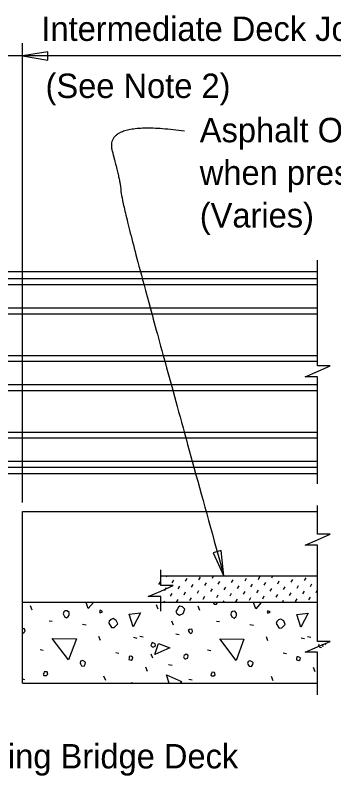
# Model space of a CAD drawing. Extents: x 21516.9 to 21586.2, y 56155.7 to 56195.
# Drawn here: x 21529.91 to 21532.55, y 56169.83 to 56176.11 of the extents above; entities that cross this region are included whole.
import ezdxf

# ---------------------------------------------------------------- set-up
doc = ezdxf.new("R2010")
doc.units = 0
for name, color, linetype in [('AdhocPoint_dp', 7, 'Continuous'), ('Border', 7, 'Continuous'), ('PlotBorder_dp', 7, 'Continuous'), ('SheetBorder_dp', 7, 'Continuous'), ('TextMisc', 7, 'Continuous')]:
    doc.layers.add(name, color=color, linetype=linetype)

msp = doc.modelspace()

# ---------------------------------------------------------------- linework, layer by layer
at = {"layer": 'AdhocPoint_dp'}
for p, q in [((21529.9739, 56170.5954), (21529.9739, 56172.0121)), ((21529.9739, 56172.0121), (21532.4121, 56172.0121)), ((21531.1155, 56171.481), (21532.4121, 56171.481)), ((21532.4121, 56171.2621), (21529.9739, 56171.2621)), ((21529.9739, 56170.5954), (21532.4121, 56170.5954))]:
    msp.add_line(p, q, dxfattribs=at)
at = {"layer": 'Border'}
for p, q in [((21531.1613, 56171.4724), (21531.1663, 56171.481)), ((21531.4314, 56171.4495), (21531.4444, 56171.4719)), ((21531.5421, 56171.4624), (21531.5528, 56171.481)), ((21531.6527, 56171.4754), (21531.6559, 56171.481)), ((21531.9228, 56171.4525), (21531.9358, 56171.4749)), ((21532.0334, 56171.4655), (21532.0424, 56171.481)), ((21532.1441, 56171.4784), (21532.1456, 56171.481)), ((21532.3035, 56171.4425), (21532.3165, 56171.4649)), ((21531.0995, 56171.4106), (21531.1125, 56171.433)), ((21531.2102, 56171.4235), (21531.2231, 56171.4459)), ((21531.3208, 56171.4365), (21531.3338, 56171.4589)), ((21531.3696, 56171.3877), (21531.3826, 56171.4101)), ((21531.4803, 56171.4006), (21531.4932, 56171.423)), ((21531.5909, 56171.4136), (21531.6039, 56171.436)), ((21531.7015, 56171.4266), (21531.7145, 56171.449)), ((21531.7504, 56171.3777), (21531.7633, 56171.4001)), ((21531.8122, 56171.4395), (21531.8251, 56171.4619)), ((21531.861, 56171.3907), (21531.874, 56171.4131)), ((21531.9716, 56171.4037), (21531.9846, 56171.426)), ((21532.0823, 56171.4166), (21532.0952, 56171.439)), ((21532.1929, 56171.4296), (21532.2059, 56171.452)), ((21532.2417, 56171.3807), (21532.2547, 56171.4031)), ((21532.3524, 56171.3937), (21532.3653, 56171.4161)), ((21531.1484, 56171.3617), (21531.1613, 56171.3841)), ((21531.259, 56171.3747), (21531.272, 56171.3971)), ((21531.3078, 56171.3259), (21531.3208, 56171.3483)), ((21531.4185, 56171.3388), (21531.4314, 56171.3612)), ((21531.5291, 56171.3518), (21531.5421, 56171.3742)), ((21531.6397, 56171.3648), (21531.6527, 56171.3872)), ((21531.6886, 56171.3159), (21531.7015, 56171.3383)), ((21531.7992, 56171.3289), (21531.8122, 56171.3513)), ((21531.9098, 56171.3419), (21531.9228, 56171.3642)), ((21532.0205, 56171.3548), (21532.0334, 56171.3772)), ((21532.1311, 56171.3678), (21532.1441, 56171.3902)), ((21532.1799, 56171.3189), (21532.1929, 56171.3413)), ((21532.2906, 56171.3319), (21532.3035, 56171.3543)), ((21532.4012, 56171.3449), (21532.4121, 56171.3638)), ((21531.1972, 56171.3129), (21531.2102, 56171.3353)), ((21531.246, 56171.2641), (21531.259, 56171.2865)), ((21531.3567, 56171.277), (21531.3696, 56171.2994)), ((21531.4673, 56171.29), (21531.4803, 56171.3124)), ((21531.5779, 56171.303), (21531.5909, 56171.3254)), ((21531.6314, 56171.2621), (21531.6397, 56171.2765)), ((21531.7374, 56171.2671), (21531.7504, 56171.2895)), ((21531.848, 56171.2801), (21531.861, 56171.3024)), ((21531.9587, 56171.293), (21531.9716, 56171.3154)), ((21532.0693, 56171.306), (21532.0823, 56171.3284)), ((21532.121, 56171.2621), (21532.1311, 56171.2795)), ((21532.2288, 56171.2701), (21532.2417, 56171.2925)), ((21532.3394, 56171.2831), (21532.3524, 56171.3055)), ((21530.0541, 56171.1989), (21530.04, 56171.2343)), ((21531.0947, 56171.2071), (21531.0806, 56171.2425)), ((21531.1418, 56171.2621), (21531.1484, 56171.2735)), ((21531.4388, 56171.1954), (21531.4247, 56171.2308)), ((21531.5283, 56171.2621), (21531.5291, 56171.2636)), ((21532.0179, 56171.2621), (21532.0205, 56171.2666)), ((21530.192, 56171.1105), (21530.2168, 56171.107)), ((21531.2202, 56171.0746), (21531.2079, 56171.1082)), ((21531.5767, 56171.107), (21531.6015, 56171.1035)), ((21530.4678, 56171.0823), (21530.4979, 56171.077)), ((21531.8525, 56171.0787), (21531.8825, 56171.0734)), ((21530.6163, 56170.9479), (21530.6039, 56170.9815)), ((21530.8903, 56170.9744), (21530.9186, 56170.9674)), ((21530.9427, 56170.9844), (21530.971, 56170.9773)), ((21531.2391, 56171.0027), (21531.2691, 56170.9974)), ((21532.001, 56170.9444), (21531.9886, 56170.978)), ((21532.275, 56170.9709), (21532.3033, 56170.9638)), ((21532.3274, 56170.9809), (21532.3557, 56170.9738)), ((21530.1178, 56170.8737), (21530.1443, 56170.8684)), ((21530.7436, 56170.8489), (21530.7701, 56170.8436)), ((21531.0488, 56170.8018), (21531.0364, 56170.8354)), ((21531.5025, 56170.8701), (21531.529, 56170.8648)), ((21532.1283, 56170.8454), (21532.1548, 56170.8401)), ((21531.0063, 56170.6922), (21530.9922, 56170.7276)), ((21531.179, 56170.7482), (21531.2108, 56170.7446)), ((21532.391, 56170.6887), (21532.3769, 56170.724)), ((21530.6605, 56170.6173), (21530.6464, 56170.6527)), ((21532.0452, 56170.6138), (21532.031, 56170.6492)), ((21529.9739, 56170.6303), (21529.9905, 56170.6262)), ((21531.3469, 56170.6297), (21531.3752, 56170.6226))]:
    msp.add_line(p, q, dxfattribs=at)
for points in [[(21530.5155, 56171.2113), (21530.499, 56171.2621)], [(21530.5585, 56171.2621), (21530.5155, 56171.2113)], [(21531.2485, 56171.17), (21531.2715, 56171.1576), (21531.3016, 56171.17), (21531.3139, 56171.2071), (21531.2963, 56171.2248), (21531.2733, 56171.2301), (21531.2627, 56171.2231), (21531.2503, 56171.2036), (21531.2415, 56171.1877), (21531.2485, 56171.17)], [(21531.5487, 56171.2621), (21531.5573, 56171.2467), (21531.5767, 56171.2484), (21531.5855, 56171.2608), (21531.5857, 56171.2621)], [(21531.9002, 56171.2078), (21531.8825, 56171.2621)], [(21531.9462, 56171.2621), (21531.9002, 56171.2078)], [(21530.3087, 56171.1671), (21530.3193, 56171.1459), (21530.337, 56171.1353), (21530.3511, 56171.1459), (21530.3582, 56171.1565), (21530.3582, 56171.1777), (21530.3423, 56171.1936), (21530.3228, 56171.1919), (21530.314, 56171.183), (21530.3087, 56171.1671)], [(21530.6145, 56171.176), (21530.634, 56171.1848), (21530.6269, 56171.1919), (21530.6145, 56171.1972), (21530.6092, 56171.1848), (21530.6145, 56171.176)], [(21530.8879, 56171.0604), (21530.8543, 56171.1647), (21530.948, 56171.1771), (21530.8879, 56171.0604)], [(21531.6934, 56171.1636), (21531.704, 56171.1424), (21531.7217, 56171.1318), (21531.7358, 56171.1424), (21531.7429, 56171.153), (21531.7429, 56171.1742), (21531.727, 56171.1901), (21531.7075, 56171.1883), (21531.6987, 56171.1795), (21531.6934, 56171.1636)], [(21531.9992, 56171.1724), (21532.0187, 56171.1813), (21532.0116, 56171.1883), (21531.9992, 56171.1936), (21531.9939, 56171.1813), (21531.9992, 56171.1724)], [(21532.2726, 56171.0569), (21532.239, 56171.1612), (21532.3327, 56171.1736), (21532.2726, 56171.0569)], [(21530.6852, 56171.0911), (21530.7082, 56171.054), (21530.7312, 56171.0557), (21530.74, 56171.0646), (21530.7595, 56171.084), (21530.7471, 56171.1141), (21530.7224, 56171.1282), (21530.7047, 56171.1212), (21530.6905, 56171.107), (21530.6852, 56171.0911)], [(21532.0699, 56171.0876), (21532.0929, 56171.0504), (21532.1159, 56171.0522), (21532.1247, 56171.061), (21532.1442, 56171.0805), (21532.1318, 56171.1105), (21532.107, 56171.1247), (21532.0894, 56171.1176), (21532.0752, 56171.1035), (21532.0699, 56171.0876)], [(21529.9739, 56171.0104), (21529.9764, 56171.008), (21529.987, 56171.0151), (21529.994, 56171.0257), (21529.9905, 56171.0434), (21529.9817, 56171.0451), (21529.9739, 56171.044)], [(21531.3504, 56171.0151), (21531.361, 56171.0045), (21531.3717, 56171.0116), (21531.3787, 56171.0222), (21531.3752, 56171.0398), (21531.3663, 56171.0416), (21531.354, 56171.0398), (21531.3434, 56171.0292), (21531.3504, 56171.0151)], [(21530.3529, 56170.787), (21530.2186, 56170.9638), (21530.4183, 56170.9621), (21530.3529, 56170.787)], [(21531.7376, 56170.7835), (21531.6032, 56170.9603), (21531.803, 56170.9585), (21531.7376, 56170.7835)], [(21531.0452, 56170.896), (21531.0576, 56170.8943), (21531.07, 56170.8996), (21531.0735, 56170.9102), (21531.0682, 56170.919), (21531.0576, 56170.9261), (21531.0452, 56170.9314), (21531.0382, 56170.9172), (21531.0346, 56170.9066), (21531.0452, 56170.896)], [(21531.0676, 56170.8312), (21531.0959, 56170.9232), (21531.1896, 56170.886), (21531.0676, 56170.8312)], [(21532.4243, 56170.9165), (21532.4228, 56170.9137), (21532.4193, 56170.9031), (21532.4299, 56170.8925)], [(21532.4555, 56170.8985), (21532.4582, 56170.9066), (21532.4529, 56170.9155), (21532.4513, 56170.9165)], [(21532.4784, 56170.9127), (21532.4796, 56170.9165)], [(21531.3151, 56170.7959), (21531.3222, 56170.7959), (21531.3363, 56170.803), (21531.3416, 56170.8189), (21531.3398, 56170.8277), (21531.3257, 56170.8348), (21531.308, 56170.8242), (21531.3045, 56170.8136), (21531.308, 56170.803), (21531.3151, 56170.7959)], [(21532.4299, 56170.8925), (21532.4423, 56170.8907), (21532.4442, 56170.8915)], [(21530.4519, 56170.7552), (21530.4607, 56170.7393), (21530.4819, 56170.7358), (21530.4908, 56170.7517), (21530.4943, 56170.7658), (21530.4855, 56170.7747), (21530.4696, 56170.7835), (21530.4537, 56170.7782), (21530.4484, 56170.7623), (21530.4519, 56170.7552)], [(21530.8514, 56170.7906), (21530.8709, 56170.7853), (21530.8832, 56170.7941), (21530.885, 56170.8065), (21530.8815, 56170.81), (21530.8673, 56170.8171), (21530.8549, 56170.8153), (21530.8532, 56170.803), (21530.8514, 56170.7906)], [(21531.8366, 56170.7517), (21531.8454, 56170.7358), (21531.8666, 56170.7322), (21531.8755, 56170.7482), (21531.879, 56170.7623), (21531.8702, 56170.7711), (21531.8543, 56170.78), (21531.8383, 56170.7747), (21531.833, 56170.7588), (21531.8366, 56170.7517)], [(21532.2361, 56170.787), (21532.2555, 56170.7817), (21532.2679, 56170.7906), (21532.2697, 56170.803), (21532.2661, 56170.8065), (21532.252, 56170.8136), (21532.2396, 56170.8118), (21532.2379, 56170.7994), (21532.2361, 56170.787)], [(21530.1496, 56170.658), (21530.1708, 56170.658), (21530.1814, 56170.6686), (21530.1761, 56170.688), (21530.1531, 56170.6898), (21530.1496, 56170.6792), (21530.1443, 56170.6704), (21530.1496, 56170.658), (21530.1461, 56170.6615)], [(21531.1842, 56170.5954), (21531.1619, 56170.6639), (21531.2874, 56170.6091), (21531.2758, 56170.5954)], [(21531.5343, 56170.6545), (21531.5555, 56170.6545), (21531.5661, 56170.6651), (21531.5608, 56170.6845), (21531.5378, 56170.6863), (21531.5343, 56170.6757), (21531.529, 56170.6668), (21531.5343, 56170.6545), (21531.5307, 56170.658)], [(21530.8822, 56170.5954), (21530.8755, 56170.5968), (21530.8715, 56170.5954)]]:
    msp.add_lwpolyline(points, dxfattribs=at)
at = {"layer": 'PlotBorder_dp'}
for p, q in [((21529.9739, 56172.0884), (21529.9739, 56175.8795)), ((21533.8765, 56175.7746), (21528.3251, 56175.7746))]:
    msp.add_line(p, q, dxfattribs=at)
for points in [[(21529.9739, 56175.7746), (21530.1821, 56175.7393), (21530.1821, 56175.8099)], [(21531.6373, 56171.4798), (21531.6158, 56171.69), (21531.5478, 56171.6712)]]:
    msp.add_lwpolyline(points, close=True, dxfattribs=at)
for points in [[(21532.4121, 56172.2416), (21532.4121, 56173.1248), (21532.3088, 56173.1248), (21532.4121, 56173.1698), (21532.5155, 56173.2148), (21532.4121, 56173.2148), (21532.4121, 56174.0878)], [(21532.4121, 56171.2647), (21532.4121, 56171.7348), (21532.3088, 56171.7348), (21532.4121, 56171.7798), (21532.5155, 56171.8248), (21532.4121, 56171.8248), (21532.4121, 56172.0622)], [(21531.1155, 56171.1901), (21531.1155, 56171.311), (21531.0122, 56171.311), (21531.1155, 56171.356), (21531.2189, 56171.401), (21531.1155, 56171.401), (21531.1155, 56171.5316)], [(21532.4121, 56170.4996), (21532.4121, 56170.8503), (21532.3088, 56170.8503), (21532.4121, 56170.8953), (21532.5155, 56170.9403), (21532.4121, 56170.9403), (21532.4121, 56171.2647)]]:
    msp.add_lwpolyline(points, dxfattribs=at)
msp.add_open_spline([(21531.3121, 56175.1531), (21530.644, 56175.2467), (21530.7843, 56174.7318), (21530.7891, 56174.591), (21531.0648, 56173.5516), (21531.6373, 56171.4798)], degree=2, dxfattribs=at)
at = {"layer": 'TextMisc'}
for p, q in [((21532.4121, 56173.9913), (21524.2717, 56173.9913)), ((21524.2717, 56173.9357), (21532.4121, 56173.9357)), ((21524.2717, 56173.8875), (21532.4121, 56173.8875)), ((21524.2717, 56173.6947), (21532.4121, 56173.6947)), ((21524.2717, 56173.6465), (21532.4121, 56173.6465)), ((21524.2717, 56173.3025), (21532.4121, 56173.3025)), ((21524.2717, 56173.2543), (21532.4121, 56173.2543)), ((21524.2717, 56173.0615), (21532.4121, 56173.0615)), ((21524.2717, 56173.0133), (21532.4121, 56173.0133)), ((21524.2717, 56172.6694), (21532.4121, 56172.6694)), ((21524.2717, 56172.6212), (21532.4121, 56172.6212)), ((21524.2717, 56172.4283), (21532.4121, 56172.4283)), ((21524.2717, 56172.3801), (21532.4121, 56172.3801)), ((21532.4121, 56172.3246), (21524.2717, 56172.3246))]:
    msp.add_line(p, q, dxfattribs=at)

# ---------------------------------------------------------------- texts
at = {"layer": 'PlotBorder_dp'}
for s, p in [('Asphalt Overlay', (21531.4381, 56175.0621)), ('when present', (21531.4381, 56174.7101)), ('(Varies)', (21531.4381, 56174.3581))]:
    msp.add_text(s, height=0.2016, dxfattribs=at).set_placement(p)
at = {"layer": 'SheetBorder_dp'}
for s, p in [('Intermediate Deck Joint', (21530.1294, 56175.8989)), ('(See Note 2)', (21530.1635, 56175.4274)), ('Existing Bridge Deck', (21529.2686, 56169.8913))]:
    msp.add_text(s, height=0.2016, dxfattribs=at).set_placement(p)

doc.saveas('drawing.dxf')
